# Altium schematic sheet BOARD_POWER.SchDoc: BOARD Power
size A4; Date: Not used; ApprovedBy: Not used; CheckedBy: Not used; Author: Not used; CompanyName: STMicroelectronics; DrawnBy: Not used; Engineer: Not used; Organization: Not used; Address1: Not used; Address2: Not used; Address3: Not used; Address4: Not used; DocumentNumber: Not used; Revision: Not used; SheetNumber: 14; SheetTotal: 16
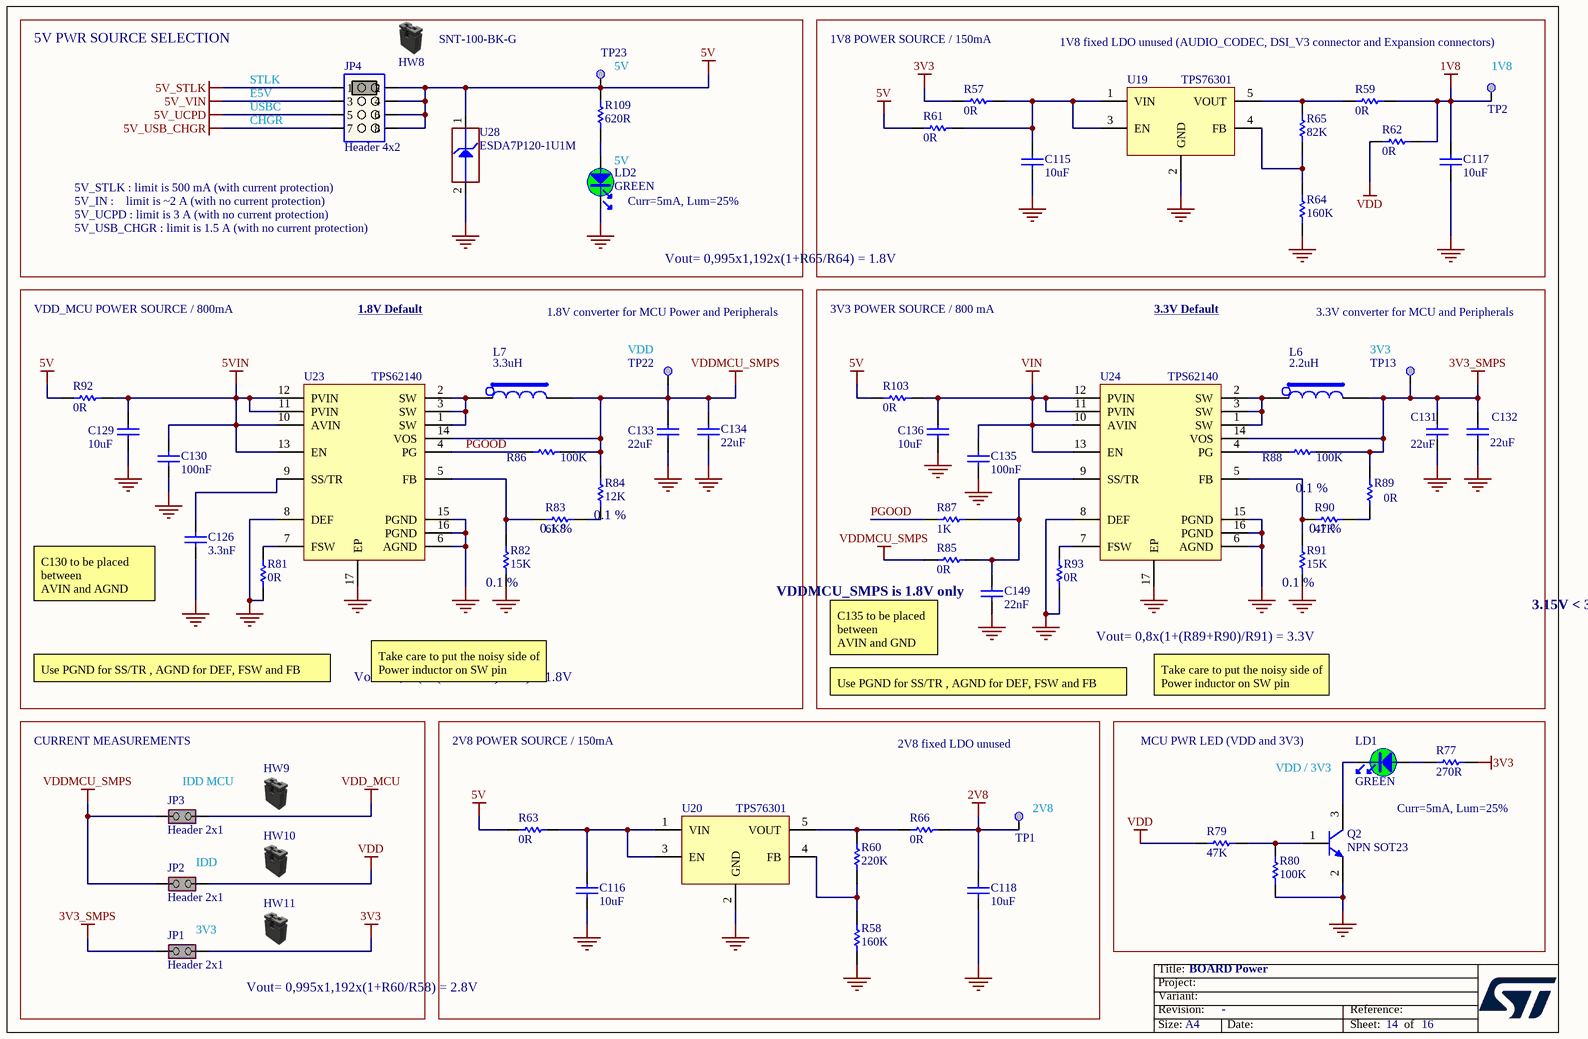
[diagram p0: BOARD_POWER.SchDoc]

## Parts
C115  value 10uF  [C0603_H0P8]  (hidden comment: Capacitor)
C116  value 10uF  [C0603_H0P8]  (hidden comment: Capacitor)
C117  value 10uF  [C0603_H0P8]  (hidden comment: Capacitor)
C118  value 10uF  [C0603_H0P8]  (hidden comment: Capacitor)
C126  value 3.3nF  [C0402]  (hidden comment: Capacitor)
C129  value 10uF  [C1206_H1P6]  (hidden comment: Capacitor)
C130  value 100nF  [C0402]  (hidden comment: Capacitor)
C131  value 22uF  [C0603_H0P8]  (hidden comment: Capacitor)
C132  value 22uF  [C0603_H0P8]  (hidden comment: Capacitor)
C133  value 22uF  [C0603_H0P8]  (hidden comment: Capacitor)
C134  value 22uF  [C0603_H0P8]  (hidden comment: Capacitor)
C135  value 100nF  [C0402]  (hidden comment: Capacitor)
C136  value 10uF  [C1206_H1P6]  (hidden comment: Capacitor)
C149  value 22nF  [C0402]  (hidden comment: Capacitor)
HW8  value SNT-100-BK-G  (hidden comment: Shunt Black 2.54mm)  (mechanical)
HW9  Shunt Black 2.54mm  (value not drawn)  (mechanical)
HW10  Shunt Black 2.54mm  (value not drawn)  (mechanical)
HW11  Shunt Black 2.54mm  (value not drawn)  (mechanical)
JP1  value Header 2x1  [CON_SAMTEC_TSW-102-07-G-S]  (hidden comment: Jumper_Header 2x1 Fitted)
JP2  value Header 2x1  [CON_SAMTEC_TSW-102-07-G-S]  (hidden comment: Jumper_Header 2x1 Fitted)
JP3  value Header 2x1  [CON_SAMTEC_TSW-102-07-G-S]  (hidden comment: Jumper_Header 2x1 Fitted)
JP4  value Header 4x2  [CON_SAMTEC_TSW-104-07-X-D]  (hidden comment: Jumper_Header 4x2 Fitted 1-2)
L6  value 2.2uH  [IND_COILCRAFT_XGL4020]  (hidden comment: INDUCTOR_POWER_WINDING)
L7  value 3.3uH  [IND_COILCRAFT_XGL4020]  (hidden comment: INDUCTOR_POWER_WINDING)
LD1  value GREEN  [LED_0603_OSRAM_LG-Q396-PS-35_GREEN_1A2K_H0P4]  (hidden comment: LED_green)
LD2  value GREEN  [LED_0603_OSRAM_LG-Q396-PS-35_GREEN_1A2K_H0P4]  (hidden comment: LED_green)
Q2  value NPN SOT23  [NPN_SOT23]  (hidden comment: 9013-SOT23)
R57  value 0R  [R0402]  (hidden comment: Resistor)
R58  value 160K  [R0402]  (hidden comment: Resistor)
R59  value 0R  [R0603]  (hidden comment: Resistor)
R60  value 220K  [R0402]  (hidden comment: Resistor)
R61  value 0R  [R0402]  (hidden comment: Resistor)
R62  value 0R  [R0603]  (hidden comment: Resistor)
R63  value 0R  [R0402]  (hidden comment: Resistor)
R64  value 160K  [R0402]  (hidden comment: Resistor)
R65  value 82K  [R0402]  (hidden comment: Resistor)
R66  value 0R  [R0603]  (hidden comment: Resistor)
R77  value 270R  [R0402]  (hidden comment: Resistor)
R79  value 47K  [R0603]  (hidden comment: Resistor)
R80  value 100K  [R0603]  (hidden comment: Resistor)
R81  value 0R  [R0402]  (hidden comment: Resistor)
R82  value 15K  [R0402]  (hidden comment: Resistor)
R83  value 6K8  [R0402]  (hidden comment: Resistor)
R84  value 12K  [R0402]  (hidden comment: Resistor)
R85  value 0R  [R0402]  (hidden comment: Resistor)
R86  value 100K  [R0402]  (hidden comment: Resistor)
R87  value 1K  [R0402]  (hidden comment: Resistor)
R88  value 100K  [R0402]  (hidden comment: Resistor)
R89  value 0R  [R0402]  (hidden comment: Resistor)
R90  value 47K  [R0402]  (hidden comment: Resistor)
R91  value 15K  [R0402]  (hidden comment: Resistor)
R92  value 0R  [R0603]  (hidden comment: Resistor)
R93  value 0R  [R0402]  (hidden comment: Resistor)
R103  value 0R  [R0603]  (hidden comment: Resistor)
R109  value 620R  [R0402]  (hidden comment: Resistor)
TP1  Test Point  [TP_SMD_1MM]  (value not drawn)  (no BOM)
TP2  Test Point  [TP_SMD_1MM]  (value not drawn)  (no BOM)
TP13  Test Point  [TP_SMD_1MM]  (value not drawn)  (no BOM)
TP22  Test Point  [TP_SMD_1MM]  (value not drawn)  (no BOM)
TP23  Test Point  [TP_SMD_1MM]  (value not drawn)  (no BOM)
U19  TPS76301  [ICC_SOT23-5L_H1P45]
U20  TPS76301  [ICC_SOT23-5L_H1P45]
U23  value TPS62140  [ICC_VQFN16-EPAD_3X3_P050]  (hidden comment: TPS62140RGTR)
U24  value TPS62140  [ICC_VQFN16-EPAD_3X3_P050]  (hidden comment: TPS62140RGTR)
U28  value ESDA7P120-1U1M  [ESD_QFN1610_2N_1K_2A]  (hidden comment: ESD-TRANSIL)

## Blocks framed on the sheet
5V PWR SOURCE SELECTION: JP4 LD2 R109 TP23 U28
Vout= 0,995x1,192x(1+R65/R64) = 1.8V: C115 C117 R57 R59 R61 R62 R64 R65 TP2 U19
VDDMCU_SMPS is 1.8V only: C126 C129 C130 C133 C134 L7 R81-R84 R86 R92 TP22 U23
3.15V < 3V3_SMPS typ. < 3.6V: C131 C132 C135 C136 C149 L6 R85 R87-R91 R93 R103 TP13 U24
Vout= 0,995x1,192x(1+R60/R58) = 2.8V: C116 C118 R58 R60 R63 R66 TP1 U20

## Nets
1V8: C117.2 R59.2 R62.2 TP2.1
2V8: C118.2 R66.2 TP1.1
3V3: JP1.2(NO) R57.1 R77.2
3V3_SMPS: C131.1 C132.2 JP1.1(COMMON) L6.2 R88.2 R89.2 TP13.1 U24.14(VOS)
5V: JP4.2 JP4.4 JP4.6 JP4.8 R61.1 R63.1 R92.1 R103.1 R109.2 TP23.1 U28.1(IO1)
5V_STLK: JP4.1
5V_UCPD: JP4.5
5V_USB_CHGR: JP4.7
5V_VIN: JP4.3
5VIN: C129.2 C130.2 R92.2 U23.10(AVIN) U23.11(PVIN) U23.12(PVIN) U23.13(EN)
GND: C115.1 C116.1 C117.1 C118.1 C126.1 C129.1 C130.1 C131.2 C132.1 C133.1 C134.1 C135.1 C136.1 C149.1 LD2.2 Q2.2(E) R58.1 R64.1 R80.1 R81.1 R82.1 R91.1 R93.1 U19.2(GND) U20.2(GND) U23.6(AGND) U23.8(DEF) U23.15(PGND) U23.16(PGND) U23.17(EP) U24.6(AGND) U24.8(DEF) U24.15(PGND) U24.16(PGND) U24.17(EP) U28.2(GND)
VDD: JP2.2(NO) R62.1 R79.1
VDD_MCU: JP3.2(NO)
VDDMCU_SMPS: C133.2 C134.2 JP2.1(COMMON) JP3.1(COMMON) L7.2 R84.1 R85.2 R86.2 TP22.1 U23.14(VOS)
VIN: C135.2 C136.2 R103.2 U24.10(AVIN) U24.11(PVIN) U24.12(PVIN) U24.13(EN)
PGOOD: R86.1 R87.2 U23.4(PG)
NetC115_2: C115.2 R57.2 R61.2 U19.1(VIN) U19.3(EN)
NetC116_2: C116.2 R63.2 U20.1(VIN) U20.3(EN)
NetC126_2: C126.2 U23.9(SS/TR)
NetC149_2: C149.2 R85.1 R87.1 U24.9(SS/TR)
NetL6_1: L6.1 U24.1(SW) U24.2(SW) U24.3(SW)
NetL7_1: L7.1 U23.1(SW) U23.2(SW) U23.3(SW)
NetLD1_1: LD1.1 R77.1
NetLD1_2: LD1.2 Q2.3(C)
NetLD2_1: LD2.1 R109.1
NetQ2_1: Q2.1(B) R79.2 R80.2
NetR58_2: R58.2 R60.1 U20.4(FB)
NetR59_1: R59.1 R65.2 U19.5(VOUT)
NetR60_2: R60.2 R66.1 U20.5(VOUT)
NetR64_2: R64.2 R65.1 U19.4(FB)
NetR81_2: R81.2 U23.7(FSW)
NetR82_2: R82.2 R83.1 U23.5(FB)
NetR83_2: R83.2 R84.2
NetR88_1: R88.1 U24.4(PG)
NetR89_1: R89.1 R90.2
NetR90_1: R90.1 R91.2 U24.5(FB)
NetR93_2: R93.2 U24.7(FSW)

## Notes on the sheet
- 1V8 POWER SOURCE / 150mA
- 1V8 fixed LDO unused (AUDIO_CODEC, DSI_V3 connector and Expansion connectors)
- STLK
- E5V
- USBC
- (near TP23) 5V
- (near TP2) 1V8
- CHGR
- (near LD2) 5V
- 5V_STLK : limit is 500 mA (with current protection)
- 5V_IN :    limit is | A (with no current protection)
- 5V_UCPD : limit is 3 A (with no current protection)
- 5V_USB_CHGR : limit is 1.5 A (with no current protection)
- (near LD2) Curr=5mA, Lum=25%
- VDD_MCU POWER SOURCE / 800mA
- 1.8V Default
- 1.8V converter for MCU Power and Peripherals
- 3V3 POWER SOURCE / 800 mA
- 3.3V Default
- 3.3V converter for MCU and Peripherals
- (near TP22) VDD
- (near TP13) 3V3
- (near R83) 0.1 %
- (near R84) 0.1 %
- (near R89) 0.1 %
- (near R90) 0.1 %
- (near R82) 0.1 %
- (near R91) 0.1 %
- (near C126) C130 to be placed between
  AVIN and AGND
- C135 to be placed between
  AVIN and GND
- Vout= 0,8x(1+(R89+R90)/R91) = 3.3V
- Use PGND for SS/TR , AGND for DEF, FSW and FB
- Take care to put the noisy side of Power inductor on SW pin
- Vout= 0,8x(1+(R83+R84)/R82) = 1.8V
- CURRENT MEASUREMENTS
- IDD MCU
- 2V8 POWER SOURCE / 150mA
- 2V8 fixed LDO unused
- MCU PWR LED (VDD and 3V3)
- VDD / 3V3
- (near TP1) 2V8
- Curr=5mA, Lum=25%
- (near JP2) IDD
- (near JP1) 3V3

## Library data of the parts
C115-C118 = MCD-02605: Capacitor, MLCC, 10uF, 10V, X5R, +/-10%, 0603, T=0.8mm; Part_Preference: Recommended; Manufacturer: YAGEO; Manufacturer_Part_Number: CC0603KRX5R6BB106; Order_Code_RS: 2006536
C126 = MCD-02628: Capacitor, MLCC, 3.3nF, 50V, X7R, +/-10%, 0402, T=0.5mm; Part_Preference: Recommended; Manufacturer: YAGEO; Manufacturer_Part_Number: CC0402KRX7R9BB332; Order_Code_RS: 1992260
C129 C136 = MCD-02610: Capacitor, MLCC, 10uF, 25V, X5R, +/-10%, 1206, T=1.6mm; Part_Preference: Recommended; Manufacturer: YAGEO; Manufacturer_Part_Number: CC1206KKX5R8BB106; Order_Code_RS: 1991983
C130 C135 = MCD-00006: Capacitor, MLCC, 100nF, 16V, X7R, +/-10%, 0402, T=0.5mm; Part_Preference: Recommended; Manufacturer: YAGEO; Manufacturer_Part_Number: CC0402KRX7R7BB104; Order_Code_RS: 616-9701; Component_Country_Of_Origin: China
C131-C134 = MCD-02607: Capacitor, MLCC, 22uF, 10V, X5R, +/-20%, 0603, T=0.8mm; Part_Preference: Recommended; Manufacturer: YAGEO; Manufacturer_Part_Number: CC0603MRX5R6BB226; Order_Code_RS: 2006627
C149 = MCD-03051: Capacitor, MLCC, 22nF, 50V, X7R, +/-10%, 0402, T=0.5mm; Part_Preference: Recommended; Manufacturer: YAGEO; Manufacturer_Part_Number: CC0402KRX7R9BB223; Order_Code_RS: NA; ShowFields: YES; ID: 5167
HW8 = MCD-00043: SHUNT 2.54mm BLACK; Part_Type: Misc; Manufacturer: SAMTEC; Part_Preference: Recommended; Component_Country_Of_Origin: China, Costa Rica, Malaysia, United States, Vietnam
HW9-HW11 = MCD-00043: SHUNT 2.54mm BLACK; Part_Type: Misc; Manufacturer: SAMTEC; Part_Preference: Recommended; Value: SNT-100-BK-G; Component_Country_Of_Origin: China, Costa Rica, Malaysia, United States, Vietnam
JP1-JP3 = MCD-00683: Header, 2x1, 2.54mm, VR, TH, T=5.84mm/2.54mm; Part_Type: Connector; Manufacturer: SAMTEC; Manufacturer_Part_Number: TSW-102-07-G-S; Part_Preference: Recommended; Order_Code_RS: 155-5312; Component_Country_Of_Origin: China, Costa Rica, Malaysia, United States, Vietnam
JP4 = MCD-00686: Header, 4x2, 2.54mm, VR, TH, T=5.84mm/2.54mm; Part_Type: Connector; Manufacturer_Part_Number: TSW-104-07-G-D; Manufacturer: SAMTEC; Part_Preference: Recommended; Order_Code_RS: 161-2260; Component_Country_Of_Origin: China, Costa Rica, Malaysia, United States, Vietnam
L6 = MCD-02582: Inductor, 2.2uH, +/-20%, 8.9A, 0R022, 4x4mm, T=2.1mm; Part_Preference: Recommended; Manufacturer: COILCRAFT; Manufacturer_Part_Number: XGL4020-222MED; ShowFields: YES; ID: 4688
L7 = MCD-02581: Inductor, 3.3uH, +/-20%, 6.6A, 0R034, 4x4mm, T=2.1mm; Part_Preference: Recommended; Manufacturer: COILCRAFT; Manufacturer_Part_Number: XGL4020-332MED; ShowFields: YES; ID: 4687
LD1 LD2 = MCD-00588: LED Green, 0603 SMD, Forward Voltage Typ=2V, Max=2.5V; Part_Type: Display; Manufacturer: OSRAM OPTO SEMICONDUCTORS; Manufacturer_Part_Number: LG Q396-PS-35; Part_Preference: Recommended; Alternate_Internal_Part_Number: MCD-02400; Component_Country_Of_Origin: Unknown; ShowFields: YES; ID: 3155
Q2 = MCD-00073: NPN Bipolar Transistor; Part_Type: IC; Manufacturer_Part_Number: BSR14; Manufacturer: ON SEMICONDUCTOR; Part_Preference: Recommended; Component_Country_Of_Origin: Unknown
R57 R61 R63 R81 R85 R93 = MCD-00052: Resistor, 0R, 0402, +/-5%, 1/16W; Part_Preference: Recommended; Manufacturer: YAGEO; Manufacturer_Part_Number: RC0402JR-070RL; Order_Code_RS: 618-5804; Component_Country_Of_Origin: China
R58 R64 = MCD-00405: Resistor, 160K, 0402, +/-1%, 1/16W; Part_Preference: Recommended; Manufacturer: YAGEO; Manufacturer_Part_Number: RC0402FR-07160KL; Component_Country_Of_Origin: China
R59 R62 R66 R92 R103 = MCD-00181: Resistor, 0R, 0603, +/- 0.5mR, 1/4W; Part_Preference: Recommended; Manufacturer: ROHM; Manufacturer_Part_Number: PMR03EZPJ000; Component_Country_Of_Origin: Philippines, Thailand
R60 = MCD-00164: Resistor, 220K, 0402, +/-1%, 1/16W; Part_Preference: Recommended; Manufacturer: YAGEO; Manufacturer_Part_Number: RC0402FR-07220KL; Component_Country_Of_Origin: China
R65 = MCD-00531: Resistor, 82K, 0402, +/-1%, 1/16W; Part_Preference: Recommended; Manufacturer: YAGEO; Manufacturer_Part_Number: RC0402FR-0782KL; Component_Country_Of_Origin: China
R77 = MCD-00441: Resistor, 270R, 0402, +/-1%, 1/16W; Manufacturer: YAGEO; Manufacturer_Part_Number: RC0402FR-07270RL; Part_Preference: Recommended; Component_Country_Of_Origin: China; ShowFields: YES; ID: 2838
R79 = MCD-00222: Resistor, 47K, 0603, 1%, 1/10W; Manufacturer_Part_Number: RC0603FR-0747KL; Manufacturer: YAGEO; Part_Preference: Recommended; Component_Country_Of_Origin: China
R80 = MCD-00223: Resistor, 100K, 0603, +/- 1%, 1/10W; Manufacturer_Part_Number: RC0603FR-07100KL; Manufacturer: YAGEO; Part_Preference: Recommended; Component_Country_Of_Origin: China
R82 R91 = MCD-02570: Resistor, 15K, 0402, +/-0.1%, 1/16W, +/-25ppm/°C; Part_Preference: Recommended; Manufacturer: YAGEO; Manufacturer_Part_Number: RT0402BRD0715KL; Order_Code_RS: 1991284
R83 = MCD-02568: Resistor, 6K8, 0402, +/-0.1%, 1/16W, +/-25ppm/°C; Part_Preference: Recommended; Manufacturer: YAGEO; Manufacturer_Part_Number: RT0402BRD076K8L; Order_Code_RS: 1991364
R84 = MCD-02567: Resistor, 12K, 0402, +/-0.1%, 1/16W, +/-25ppm/°C; Part_Preference: Recommended; Manufacturer: YAGEO; Manufacturer_Part_Number: RT0402BRD0712KL
R86 R88 = MCD-00059: Resistor, 100K, 0402, +/-1%, 1/16W; Part_Preference: Recommended; Manufacturer: YAGEO; Manufacturer_Part_Number: RC0402FR-07100KL; Component_Country_Of_Origin: China
R87 = MCD-00061: Resistor, 1K, 0402, +/-1%,1/16W; Part_Preference: Recommended; Manufacturer: YAGEO; Manufacturer_Part_Number: RC0402FR-071KL; Component_Country_Of_Origin: China; ShowFields: YES; ID: 2532
R89 = MCD-00052: Resistor, 0R, 0402, +/-5%, 1/16W; Part_Preference: Recommended; Manufacturer: YAGEO; Manufacturer_Part_Number: RC0402JR-070RL; Order_Code_RS: 618-5804; Component_Country_Of_Origin: China; ShowFields: YES; ID: 2540
R90 = MCD-02550: Resistor, 47K, 0402, +/-0.1%, 1/16W, +/-25ppm/°C; Part_Preference: Recommended; Manufacturer: YAGEO; Manufacturer_Part_Number: RT0402BRD0747KL; Order_Code_RS: 1991342
R109 = MCD-00499: Resistor, 620R, 0402, +/-1%, 1/16W; Manufacturer: YAGEO; Manufacturer_Part_Number: RC0402FR-07620RL; Part_Preference: Recommended; Component_Country_Of_Origin: China; ShowFields: YES; ID: 2781
TP1 TP2 TP13 TP22 TP23 = MCD-00074: Test Point 1mm; Part_Type: Misc; Part_Preference: Recommended
U19 U20 = MCD-02175: LDO VOLTAGE REGULATOR, Adjustable, 150mA,; Part_Type: IC; Manufacturer_Part_Number: TPS76301DBVT; Manufacturer: TEXAS INSTRUMENTS; Part_Preference: Recommended; Component_Country_Of_Origin: China
U23 U24 = MCD-02580: Buck converter, 2A, 3V to 17V input, Fsw 1.25/2.5 MHz, 3x3 VQFN16; Part_Type: IC; Part_Preference: Recommended; Manufacturer: TEXAS INSTRUMENTS
U28 = MCD-01026: High power transient voltage suppressor; Part_Type: Diode; Manufacturer: STMICROELECTRONICS; BMS_Part_Number: 9179046; Part_Preference: Recommended; Manufacturer_HQ_COO: EU; Component_Country_Of_Origin: China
